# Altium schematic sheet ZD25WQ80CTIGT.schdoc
size 127 x 101 mm
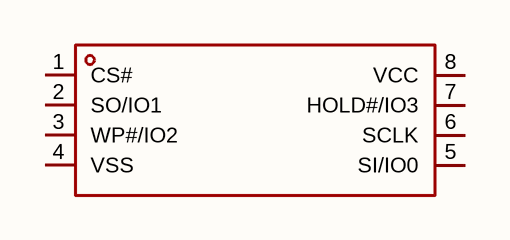
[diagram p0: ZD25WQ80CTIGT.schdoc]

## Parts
U?  zd25wq80ctigt  [SOP-8_L4.9-W3.9-P1.27-LS6.0-BL]  (value not drawn)

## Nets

Not connected (* = marked no-connect by the designer): U? 1(CS#) 2(SO/IO1) 3(WP#/IO2) 4(VSS) 5(SI/IO0) 6(SCLK) 7(HOLD#/IO3) 8(VCC)

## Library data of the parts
U? = zd25wq80ctigt: 接口类型:SPI;存储容量:8Mbit;时钟频率(fc):104MHz;; Manufacturer: Zetta(澜智); AddInBom: yes; ModelId: 75c24a7891ee4dd6bdac16a7163ff87e; ModelName: SOP-8_L4.9-W3.9-P1.27-LS6.0-BL-1; ModelTransform: 192.913,236.22,0,0,0,0,-0.393,2.749,0; Interface: SPI; Memory Size: 8Mbit; Clock Frequency: 104MHz; Voltage - Supply: 1.65V~3.6V; Standby Supply Current: 1.3uA; Program / Erase Cycles: 100000次; Page Programming Time (Tpp): 1.5ms; Data Retention - TDR (Year): 20年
